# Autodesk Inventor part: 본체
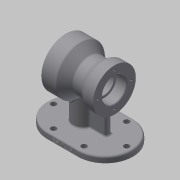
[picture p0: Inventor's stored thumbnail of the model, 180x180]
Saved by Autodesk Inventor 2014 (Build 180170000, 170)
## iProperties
Created: 2020-01
Part Number: 본체
Material: Generic
Document SubType Name: Modeling
Designer: kh
Density: 1 g/cm^3
Appearance: Default
Mass: 347.447 g
Surface Area: 654.889 cm^2
Volume: 347.447 cm^3
Author: kh
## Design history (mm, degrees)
sketch "Sketch1"
  geometry: L1 (25, 45)-(-25, 45); L2 (-25, 45)-(-25, -45); L3 (-25, -45)-(25, -45); L4 (25, -45)-(25, 45); L5 (25, 45)-(-25, -45); L6 (-25, 45)-(25, -45); L7 (0, 0)-(-25, 0); C1 r 45 at (-25, 0); C2 r 45 at (25, 0); 1 further point
  constraints: 14 end point, 4 midpoint, 2 centre point, 2 coincident, 2 parallel, 2 perpendicular, 1 horizontal
  dimensions: "d0" = 50 distance of L1.start L1.end; "d1" = 90 distance of L1.end L2.end; "d2" = 90 diameter of C1; "d3" = 90 diameter of C2
extrude "Extrusion1" new body sketch "Sketch1" distance "d4" = 10; taper "d5" = 0 deg
sketch "Sketch2"
  geometry: L1 (0, 0)-(0, 80); L2 (118.837, 80)-(-118.837, 80); L3 (40, 80)-(40, 120); L4 (40, 120)-(16, 120); L5 (16, 120)-(1.103, 107.5); L6 (1.103, 107.5)-(-13.289, 107.5); L7 (-13.289, 107.5)-(-24, 115); L8 (-24, 115)-(-40, 115); L9 (-40, 115)-(-40, 80); L10 (40, 80)-(-40, 80); L11 (70, 0)-(70, 10) reference; L12 (-70, 0)-(-70, 10) reference; L13 (-30, 80)-(-30, -1.918)
  constraints: 22 end point, 6 perpendicular, 3 point on line, 2 parallel, 1 midpoint, 1 vertical
  dimensions: "d6" = 80 distance of L1.end L1.start; "d7" = 24 distance of L3.end L4.end; "d8" = 16 distance of L7.end L8.end; "d9" = 80 distance between parallel lines of L9 L3; "d10" = 55 diameter of L6 L2; "d11" = 80 diameter of L4 L2; "d12" = 70 diameter of L8 L2; "d13" = 30 horizontal distance of L11.start L3.start; "d14" = 10 distance between parallel lines of L13 L9; "d15" = 40 deg angle of L6 L5; "d16" = 35 deg angle of L7 L6
revolve "Revolution1" sketch "Sketch2" stored, may be unused: angle "d17" = 90 deg
sketch "Sketch3"
  geometry: L1 (-25, -45)-(25, -45) reference; L2 (-70, 0)-(76.908, 0); L3 (30, 5)-(-9.895, 5); L4 (-9.895, 5)-(-9.895, -5); L5 (-9.895, -5)-(30, -5); L6 (30, -5)-(30, 5); L7 (30, 5)-(-9.895, -5); L8 (-9.895, 5)-(30, -5); L9 (40, 35)-(40, -35) reference; C1 r 16 at (-12, 0); A1 r 45 centre (-25, 0) between (-25, 45) and (-25, -45) reference; A2 r 45 centre (-25, 0) between (-25, 45) and (-25, -45) reference; 2 further points
  constraints: 14 end point, 3 parallel, 2 midpoint, 1 centre point, 1 horizontal, 1 horizontal alignment, 1 perpendicular, 1 point on circle, 1 point on line
  dimensions: "d36" = 58 distance of L2.start C1.centre; "d37" = 10 distance of L5.end L3.start; "d38" = 10 horizontal distance of L5.end L9.end; "d85" = 32 diameter of C1
extrude "Extrusion2" join sketch "Sketch3" distance "d39" = 80; taper "d40" = 0 deg
hole "Hole1" diameter "d20" = 32; stored, may be unused: countersink angle "d24" = 90 deg, drill point angle "d26" = 0 deg; dims "d18" = 10, "d19" = 10, "d21" = 6, "d22" = 40, "d23" = 17, "d25" = 8
hole "Hole2" diameter "d29" = 52; stored, may be unused: countersink angle "d33" = 90 deg, drill point angle "d35" = 0 deg; dims "d27" = 10, "d28" = 10, "d30" = 6, "d31" = 40, "d32" = 17, "d34" = 20
sketch "Sketch4"
  geometry: L1 (0, 0)-(50, 0) reference; 3 further points
  constraints: 1 midpoint, 1 vertical alignment, 1 other
  dimensions: "d81" = 4 distance of point (25, 4) point (25, 0)
emboss "Emboss1" sketch "Sketch4" dims "d41" = 0.5, "d42" = 0
sketch "Sketch5"
  geometry: C1 r 20 at (0, 0) reference; 2 further points
  constraints: 1 horizontal alignment
  dimensions: "d43" = 27.5 distance of point (-27.5, 0) C1.centre
hole "Hole3" sketch "Sketch5" at (-27.5, 0) diameter "d44" = 3.242; stored, may be unused: countersink angle "d48" = 90 deg, drill point angle "d50" = 118 deg; dims "d45" = 9, "d46" = 40, "d47" = 17, "d49" = 11
pattern_circular "Circular Pattern1" dims angle "d52" = 360 deg
sketch "Sketch6"
  geometry: C1 r 26 at (0, 0) reference; 2 further points
  constraints: 1 horizontal alignment
  dimensions: "d54" = 33 distance of C1.centre point (33, 0)
hole "Hole4" sketch "Sketch6" at (33, 0) diameter "d55" = 3.242; stored, may be unused: countersink angle "d59" = 90 deg, drill point angle "d61" = 118 deg; dims "d56" = 9, "d57" = 40, "d58" = 17, "d60" = 11
pattern_circular "Circular Pattern2" dims angle "d63" = 360 deg
chamfer "Chamfer1" distance "d65" = 1; stored, may be unused: second distance "d66" = 2, angle "d67" = 45 deg
fillet "Fillet1" dims "d68" = 0.3
fillet "Fillet2" dims "d69" = 3
sketch "Sketch7"
  geometry: L1 (27, -5)-(5.234, -5) reference; L2 (0, 0)-(0, 43.524); L3 (-12, 0)-(80.521, 0); L4 (0, 0)-(-70, 0); L5 (0, 0)-(70, 0); C1 r 4.5 at (-25, 35); C2 r 4.5 at (25, 35); C3 r 4.5 at (-25, -35); C4 r 4.5 at (25, -35); C5 r 4.5 at (-60, 0); C6 r 4.5 at (60, 0); A1 r 45 centre (25, 0) between (25, -45) and (25, 45) reference; A2 r 45 centre (-25, 0) between (-25, 45) and (-25, -45) reference; A3 r 16 centre (-12, 0) between (2.513, 6.737) and (2.513, -6.737) reference
  constraints: 8 end point, 6 centre point, 2 horizontal alignment, 2 perpendicular, 2 point on circle, 2 point on line, 2 symmetric about line, 1 vertical alignment, 2 other
  dimensions: "d70" = 9 diameter of C1; "d71" = 9 diameter of C2; "d72" = 50 distance of C2.centre C1.centre; "d73" = 10 distance of A2.start C1.centre; "d75" = 9 diameter of C5; "d76" = 10 distance of L4.end C5.centre; "d77" = 9 diameter of C6; "d78" = 10 distance of L5.end C6.centre
extrude "Extrusion3" cut sketch "Sketch7" distance "d79" = 80; taper "d80" = 0 deg
fillet "Fillet3" dims "d82" = 3
fillet "Fillet4" dims "d83" = 3
fillet "Fillet5" dims "d84" = 3
body "Solid1"
